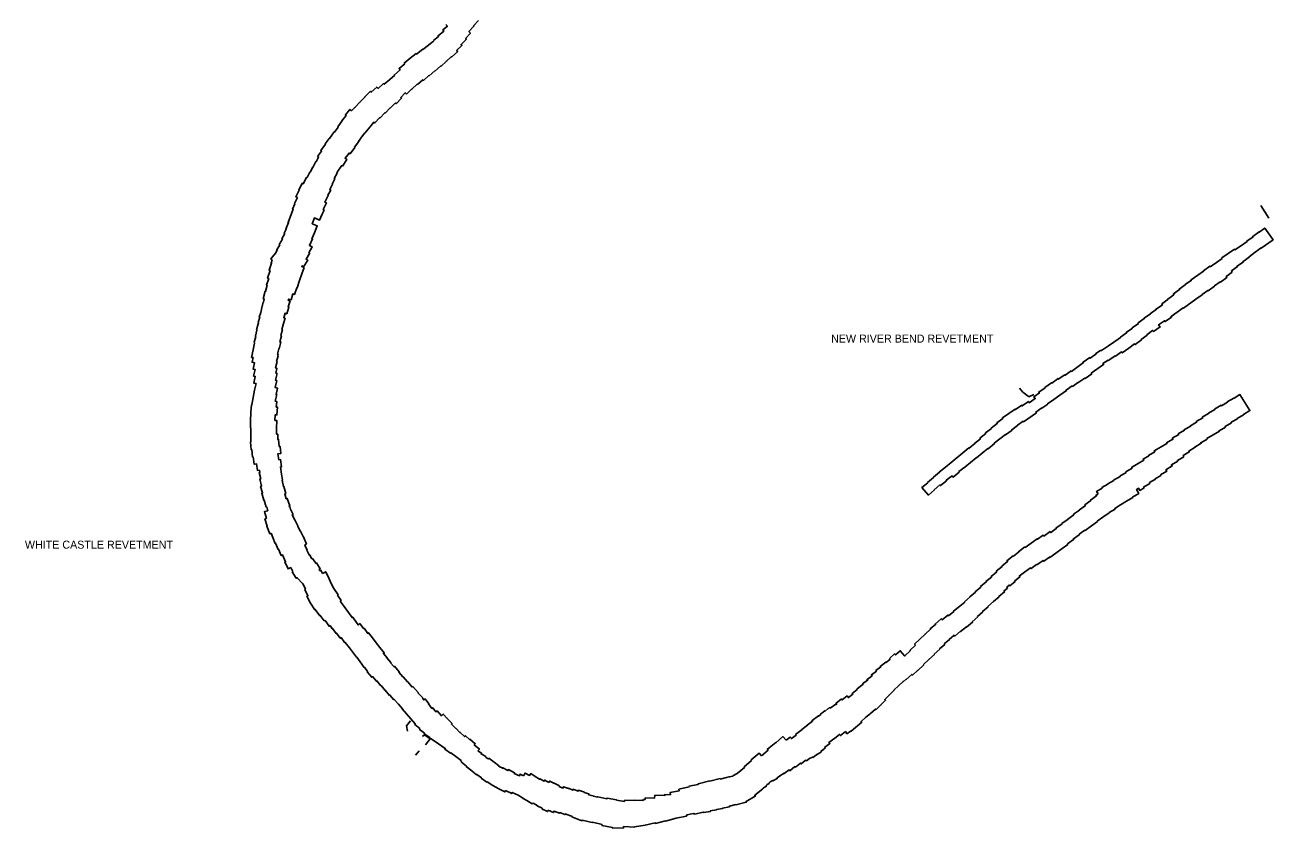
# Model space of a CAD drawing. Extents: x 2650582 to 3923188, y 277893 to 989177.
# Drawn here: x 3328264 to 3353216, y 609154 to 625211 of the extents above; entities that cross this region are included whole.
import ezdxf

# ---------------------------------------------------------------- set-up
doc = ezdxf.new("R2010")
doc.units = 0
doc.layers.add('Level 3', color=7, linetype='Continuous')

msp = doc.modelspace()

# ---------------------------------------------------------------- linework, layer by layer
at = {"layer": 'Level 3'}
for points in [[(3335892, 623830), (3335995, 623932), (3336000, 623927), (3336106, 624026), (3336111, 624021), (3336216, 624117), (3336229, 624103), (3336339, 624200), (3336344, 624195), (3336455, 624292), (3336457, 624289), (3336569, 624390), (3336577, 624381), (3336693, 624484), (3336689, 624489), (3336787, 624577), (3336792, 624570), (3336915, 624678), (3336894, 624701), (3337001, 624801), (3336982, 624821), (3337089, 624927), (3337073, 624943), (3337170, 625050), (3337138, 625079), (3337238, 625188), (3337233, 625192), (3337331, 625302)], [(3336677, 625219), (3336708, 625186), (3336619, 625114), (3336639, 625089), (3336523, 624996), (3336533, 624983), (3336432, 624900), (3336435, 624896), (3336329, 624809), (3336331, 624806), (3336221, 624720), (3336216, 624726), (3336093, 624629), (3336082, 624642), (3335964, 624546), (3335963, 624548), (3335846, 624449), (3335856, 624437), (3335743, 624343), (3335764, 624317), (3335650, 624214), (3335657, 624206)], [(3335657, 624206), (3335560, 624121), (3335558, 624123), (3335447, 624026), (3335435, 624040), (3335323, 623941), (3335296, 623970), (3335188, 623867), (3335169, 623886), (3335057, 623772), (3335060, 623769), (3334967, 623672), (3334965, 623674), (3334857, 623562), (3334859, 623560), (3334795, 623492)], [(3335013, 622997), (3335056, 623051), (3335060, 623048), (3335159, 623167), (3335156, 623170), (3335240, 623270), (3335259, 623253), (3335349, 623357), (3335357, 623350), (3335456, 623456), (3335464, 623449), (3335562, 623554), (3335568, 623548), (3335670, 623651), (3335685, 623636), (3335792, 623748), (3335777, 623763), (3335866, 623856), (3335892, 623830)], [(3334795, 623492), (3334759, 623521), (3334672, 623414), (3334684, 623404), (3334596, 623292), (3334602, 623287), (3334519, 623174), (3334525, 623170), (3334451, 623068), (3334446, 623072), (3334350, 622941), (3334348, 622943), (3334266, 622832), (3334270, 622829), (3334178, 622702), (3334195, 622689), (3334114, 622582)], [(3334531, 622309), (3334598, 622399), (3334609, 622391), (3334701, 622518), (3334663, 622545), (3334742, 622651), (3334763, 622636), (3334857, 622763), (3334853, 622766), (3334936, 622880), (3334930, 622884), (3335013, 622997), (3335013, 622997)], [(3334114, 622582), (3334133, 622568), (3334084, 622477), (3334082, 622478), (3334020, 622364), (3334017, 622366), (3333965, 622266), (3333961, 622269), (3333903, 622160), (3333895, 622164), (3333828, 622036), (3333806, 622046), (3333742, 621907), (3333744, 621906), (3333681, 621773), (3333710, 621758), (3333651, 621641)], [(3334203, 621427), (3334245, 621510), (3334228, 621519), (3334291, 621652), (3334262, 621665), (3334326, 621804), (3334322, 621806), (3334377, 621910), (3334358, 621920), (3334414, 622025), (3334406, 622029), (3334460, 622132), (3334446, 622139), (3334505, 622249), (3334500, 622253), (3334531, 622309)], [(3333651, 621641), (3333659, 621637), (3333615, 621531), (3333625, 621526), (3333572, 621386), (3333572, 621386), (3333525, 621264), (3333535, 621260), (3333482, 621131), (3333486, 621129), (3333445, 621046), (3333458, 621041), (3333401, 620934), (3333410, 620929), (3333346, 620821), (3333359, 620813), (3333297, 620713), (3333309, 620705), (3333274, 620650), (3333182, 620533), (3333209, 620512)], [(3352974, 621604), (3353134, 621349)], [(3333848, 620361), (3333796, 620381), (3333803, 620394), (3333834, 620374), (3333916, 620507), (3333884, 620526), (3333954, 620644), (3333942, 620652), (3334006, 620773), (3333950, 620803), (3334013, 620932), (3334002, 620938), (3334049, 621053), (3334051, 621053), (3334108, 621198), (3334007, 621237), (3334050, 621352), (3334155, 621309), (3334203, 621427)], [(3353069, 621451), (3353055, 621474)], [(3352400, 620270), (3352382, 620294), (3352505, 620379), (3352497, 620389), (3352622, 620476), (3352616, 620483), (3352740, 620570), (3352736, 620576), (3352860, 620665), (3352856, 620669), (3352976, 620754), (3352979, 620749), (3353216, 620915), (3353051, 621150), (3352941, 621070), (3352939, 621072), (3352811, 620982), (3352816, 620976), (3352694, 620889), (3352698, 620881), (3352562, 620788), (3352455, 620714), (3352443, 620729), (3352191, 620552), (3352198, 620543)], [(3333209, 620512), (3333185, 620449), (3333193, 620446), (3333143, 620306), (3333164, 620299), (3333115, 620147), (3333137, 620140), (3333093, 620011), (3333104, 620007), (3333070, 619884), (3333066, 619886), (3333023, 619733)], [(3333527, 619705), (3333534, 619731), (3333585, 619717), (3333617, 619834), (3333652, 619822), (3333698, 619956), (3333707, 619953), (3333755, 620102), (3333752, 620103), (3333800, 620237), (3333848, 620361)], [(3352198, 620543), (3352084, 620461), (3352082, 620463), (3351957, 620377), (3351952, 620385), (3351822, 620296), (3351828, 620287), (3351712, 620206), (3351710, 620208), (3351578, 620118), (3351584, 620108), (3351459, 620023), (3351462, 620018), (3351340, 619931), (3351347, 619919), (3351223, 619832), (3351233, 619816), (3351110, 619730), (3351115, 619722), (3350993, 619635), (3351005, 619618), (3350879, 619531), (3350884, 619526), (3350760, 619437), (3350764, 619432), (3350638, 619346), (3350641, 619341), (3350518, 619254), (3350525, 619243), (3350401, 619157), (3350405, 619151), (3350281, 619063), (3350288, 619053), (3350166, 618968), (3350168, 618965), (3350116, 618928), (3350034, 618872), (3349927, 618794), (3349924, 618797), (3349863, 618756), (3349783, 618700), (3349776, 618709)], [(3349918, 618508), (3349925, 618499), (3349936, 618506), (3350060, 618594), (3350063, 618590), (3350185, 618678), (3350200, 618655), (3350334, 618748), (3350331, 618752), (3350448, 618835), (3350456, 618822), (3350585, 618914), (3350579, 618921), (3350700, 619009), (3350695, 619018), (3350809, 619102), (3350823, 619083), (3350956, 619174), (3350929, 619216), (3351046, 619297), (3351057, 619279), (3351188, 619371), (3351177, 619385), (3351298, 619471), (3351301, 619466), (3351422, 619553), (3351425, 619550), (3351674, 619726), (3351673, 619728), (3351798, 619818), (3351797, 619820), (3351913, 619903), (3351917, 619897), (3352047, 619989), (3352045, 619993), (3352161, 620074), (3352164, 620070), (3352294, 620163), (3352281, 620180), (3352400, 620270)], [(3333023, 619733), (3333046, 619727), (3333032, 619670), (3333029, 619671), (3332992, 619526), (3332995, 619525), (3332978, 619461), (3332949, 619368), (3332957, 619366), (3332929, 619259), (3332931, 619258), (3332924, 619234), (3332927, 619233), (3332895, 619112), (3332902, 619110), (3332871, 618989), (3332876, 618988), (3332874, 618982), (3332878, 618981), (3332868, 618937), (3332849, 618866), (3332851, 618865), (3332848, 618852), (3332851, 618851), (3332824, 618713), (3332825, 618713), (3332796, 618565), (3332827, 618559)], [(3333323, 618593), (3333318, 618594), (3333324, 618625), (3333315, 618627), (3333337, 618736), (3333343, 618735), (3333379, 618869), (3333358, 618874), (3333390, 618996), (3333378, 618999), (3333410, 619119), (3333400, 619122), (3333431, 619243), (3333465, 619348), (3333436, 619358), (3333465, 619447), (3333497, 619437), (3333540, 619570), (3333526, 619574), (3333565, 619693), (3333527, 619705)], [(3332827, 618559), (3332805, 618467), (3332851, 618456), (3332826, 618331), (3332865, 618324), (3332835, 618191), (3332867, 618184), (3332838, 618050), (3332883, 618040), (3332853, 617907), (3332856, 617906), (3332826, 617763), (3332824, 617763), (3332802, 617615), (3332793, 617616), (3332780, 617467), (3332778, 617468), (3332770, 617292), (3332774, 617292), (3332771, 617157), (3332778, 617157), (3332780, 617023), (3332778, 617023), (3332780, 616876), (3332775, 616875), (3332789, 616719), (3332797, 616720), (3332816, 616572), (3332823, 616573), (3332848, 616426), (3332895, 616434), (3332916, 616302), (3332950, 616307)], [(3333395, 616230), (3333375, 616375), (3333394, 616378), (3333370, 616524), (3333340, 616519), (3333320, 616637), (3333380, 616645), (3333363, 616783), (3333346, 616781), (3333334, 616924), (3333319, 616923), (3333318, 617032), (3333294, 617032), (3333292, 617143), (3333293, 617143), (3333297, 617304), (3333262, 617304), (3333267, 617416), (3333301, 617413), (3333315, 617570), (3333286, 617572), (3333301, 617682), (3333269, 617686), (3333297, 617819), (3333283, 617822), (3333311, 617950), (3333267, 617960), (3333298, 618101), (3333275, 618106), (3333305, 618241), (3333282, 618249), (3333301, 618345), (3333274, 618356), (3333303, 618479), (3333294, 618481), (3333323, 618593)], [(3349776, 618709), (3349668, 618634), (3349673, 618627), (3349558, 618546), (3349550, 618559), (3349418, 618469), (3349425, 618459), (3349184, 618285), (3349180, 618294), (3349057, 618206), (3349051, 618215), (3348923, 618128), (3348917, 618139), (3348793, 618052), (3348789, 618058), (3348654, 617963), (3348658, 617958), (3348533, 617872), (3348546, 617854), (3348436, 617777), (3348461, 617741), (3348343, 617658), (3348326, 617683), (3348199, 617594), (3348191, 617608), (3348068, 617521), (3348060, 617532), (3347806, 617357), (3347815, 617343), (3347694, 617254), (3347703, 617241), (3347581, 617152), (3347586, 617145), (3347465, 617054), (3347472, 617044), (3347355, 616950)], [(3347517, 616738), (3347644, 616840), (3347639, 616846), (3347755, 616937), (3347753, 616939), (3347865, 617024), (3347870, 617016), (3347997, 617111), (3347991, 617119), (3348110, 617200), (3348106, 617206), (3348223, 617287), (3348230, 617278), (3348485, 617456), (3348475, 617472), (3348593, 617555), (3348596, 617551), (3348711, 617632), (3348707, 617636), (3348832, 617721), (3348830, 617724), (3348954, 617812), (3348956, 617809), (3349084, 617900), (3349078, 617909), (3349198, 617993), (3349205, 617983), (3349328, 618069), (3349330, 618066), (3349454, 618152), (3349460, 618144), (3349591, 618235), (3349582, 618248), (3349829, 618422), (3349816, 618439), (3349918, 618508)], [(3348149, 617950), (3348216, 617870), (3348319, 617789), (3348336, 617778), (3348434, 617820)], [(3351430, 616577), (3351416, 616600), (3351542, 616674), (3351532, 616692), (3351658, 616766), (3351654, 616772), (3351780, 616846), (3351772, 616859), (3351897, 616932), (3351893, 616940), (3352019, 617014), (3352016, 617018), (3352142, 617092), (3352138, 617098), (3352264, 617172), (3352256, 617185), (3352382, 617259), (3352378, 617266), (3352504, 617339), (3352500, 617345), (3352627, 617418), (3352625, 617422), (3352752, 617502), (3352553, 617820), (3352436, 617747), (3352433, 617752), (3352298, 617674), (3352302, 617666), (3352185, 617598), (3352181, 617606), (3352046, 617527), (3352049, 617522), (3351922, 617448), (3351926, 617441), (3351801, 617368), (3351809, 617354), (3351682, 617280), (3351688, 617269), (3351563, 617196), (3351566, 617189), (3351440, 617116), (3351445, 617108), (3351320, 617034), (3351329, 617020), (3351202, 616946)], [(3347355, 616950), (3347365, 616938), (3347249, 616844), (3347251, 616841), (3347139, 616749), (3347135, 616753), (3347017, 616655), (3347014, 616659), (3346779, 616464), (3346781, 616460), (3346668, 616368), (3346664, 616372), (3346543, 616272), (3346546, 616268), (3346426, 616169), (3346429, 616164), (3346309, 616061), (3346312, 616057), (3346197, 615961), (3346326, 615812), (3346446, 615916), (3346443, 615919), (3346555, 616015), (3346567, 616000), (3346690, 616099), (3346683, 616107), (3346798, 616196), (3346819, 616172), (3346943, 616272), (3346936, 616280), (3347052, 616369), (3347283, 616559), (3347287, 616554), (3347515, 616741), (3347517, 616738)], [(3351202, 616946), (3351213, 616927), (3351088, 616854), (3351095, 616842), (3350978, 616774), (3350977, 616775), (3350842, 616696), (3350853, 616677), (3350727, 616603), (3350731, 616596), (3350619, 616531), (3350632, 616509), (3350522, 616444), (3350521, 616445), (3350386, 616366), (3350397, 616347), (3350272, 616274), (3350278, 616264), (3350151, 616189), (3350156, 616182), (3350029, 616108), (3350031, 616104), (3349911, 616035), (3349913, 616032), (3349794, 615962), (3349800, 615951), (3349688, 615885), (3349717, 615836)], [(3349939, 615461), (3350059, 615531), (3350050, 615546), (3350169, 615616), (3350167, 615619), (3350286, 615688), (3350285, 615690), (3350411, 615764), (3350406, 615772), (3350532, 615846), (3350487, 615923), (3350526, 615947), (3350551, 615905), (3350637, 615956), (3350628, 615971), (3350754, 616045), (3350745, 616061), (3350864, 616131), (3350860, 616137), (3350973, 616203), (3350966, 616216), (3351092, 616289), (3351074, 616319), (3351200, 616393), (3351185, 616418), (3351312, 616492), (3351305, 616504), (3351430, 616577)], [(3332950, 616307), (3332960, 616267), (3332944, 616263), (3332976, 616133), (3332959, 616128), (3332995, 615993), (3332975, 615986), (3333015, 615854), (3332998, 615849), (3333040, 615710), (3333045, 615711), (3333087, 615572), (3333096, 615575), (3333120, 615499)], [(3333574, 615527), (3333557, 615581), (3333550, 615579), (3333544, 615590), (3333556, 615595), (3333503, 615744), (3333488, 615739), (3333460, 615837), (3333478, 615843), (3333436, 615982), (3333431, 615981), (3333405, 616108), (3333410, 616109), (3333392, 616230), (3333395, 616230)], [(3349717, 615836), (3349678, 615810), (3349687, 615797), (3349569, 615712), (3349575, 615704), (3349453, 615619), (3349464, 615603), (3349344, 615518), (3349349, 615512), (3349229, 615427), (3349235, 615418), (3349114, 615332), (3349117, 615328), (3348995, 615243), (3348999, 615237), (3348874, 615149), (3348881, 615140), (3348771, 615061), (3348757, 615081), (3348634, 614992), (3348619, 615012), (3348506, 614928), (3348499, 614937), (3348382, 614850), (3348380, 614852), (3348260, 614765), (3348254, 614774)], [(3333120, 615499), (3333052, 615481), (3333090, 615344), (3333062, 615336), (3333104, 615190), (3333098, 615187), (3333156, 615039), (3333184, 615050)], [(3333894, 614829), (3333833, 614975), (3333829, 614973), (3333772, 615092), (3333767, 615090), (3333717, 615191), (3333719, 615193), (3333668, 615301), (3333669, 615301), (3333608, 615418), (3333623, 615425), (3333574, 615527)], [(3348488, 614426), (3348494, 614417), (3348617, 614505), (3348630, 614487), (3348746, 614573), (3348753, 614563), (3348870, 614648), (3348871, 614647), (3349002, 614742), (3348999, 614746), (3349110, 614826), (3349104, 614835), (3349228, 614923), (3349221, 614933), (3349345, 615020), (3349340, 615027), (3349455, 615109), (3349458, 615105), (3349586, 615196), (3349584, 615199), (3349704, 615284), (3349701, 615288), (3349815, 615368), (3349814, 615369), (3349940, 615459), (3349939, 615461)], [(3333184, 615050), (3333216, 614963), (3333218, 614964), (3333263, 614844), (3333271, 614847), (3333324, 614724), (3333332, 614728), (3333388, 614602), (3333415, 614614), (3333473, 614479), (3333462, 614474), (3333524, 614336), (3333580, 614362)], [(3334211, 614246), (3334181, 614309), (3334159, 614298), (3334143, 614323), (3334166, 614338), (3334091, 614456), (3334076, 614447), (3334011, 614545), (3334000, 614538), (3333972, 614580), (3333956, 614614), (3333952, 614611), (3333939, 614630), (3333936, 614628), (3333899, 614710), (3333903, 614712), (3333857, 614813), (3333894, 614829)], [(3348254, 614774), (3348124, 614675), (3348128, 614668), (3348026, 614592), (3348023, 614596), (3347894, 614499), (3347908, 614480), (3347793, 614387), (3347798, 614381), (3347683, 614288), (3347692, 614278), (3347581, 614185), (3347590, 614173), (3347477, 614080), (3347481, 614075), (3347368, 613980), (3347375, 613972), (3347261, 613878), (3347268, 613870), (3347157, 613777), (3347160, 613774), (3347048, 613677), (3347053, 613671), (3346954, 613587), (3346951, 613590), (3346829, 613492), (3346833, 613486), (3346724, 613399), (3346714, 613411), (3346603, 613318), (3346584, 613340), (3346465, 613238), (3346472, 613230), (3346361, 613137), (3346369, 613127), (3346260, 613032), (3346262, 613030), (3346152, 612929), (3346154, 612927), (3346048, 612827), (3346067, 612808), (3345958, 612707), (3345964, 612700)], [(3333580, 614362), (3333616, 614280), (3333608, 614274), (3333689, 614147), (3333707, 614158), (3333815, 614043), (3333816, 614045)], [(3346234, 612415), (3346228, 612421), (3346337, 612521), (3346336, 612522), (3346445, 612625), (3346441, 612629), (3346553, 612731), (3346548, 612736), (3346651, 612825), (3346641, 612836), (3346745, 612923), (3346743, 612926), (3346839, 613008), (3346852, 612993), (3346964, 613088), (3346969, 613082), (3347084, 613174), (3347086, 613172), (3347208, 613270), (3347201, 613279), (3347312, 613374), (3347305, 613382), (3347417, 613479), (3347410, 613486), (3347520, 613578), (3347514, 613586), (3347629, 613681), (3347625, 613685), (3347739, 613780), (3347736, 613784), (3347847, 613876), (3347834, 613891), (3347910, 613953), (3347894, 613972), (3347942, 614013), (3347956, 613995), (3348055, 614075), (3348045, 614088), (3348154, 614176), (3348141, 614193), (3348246, 614272), (3348248, 614268), (3348366, 614356), (3348377, 614342), (3348488, 614426)], [(3334568, 613692), (3334587, 613705), (3334513, 613808), (3334524, 613815), (3334441, 613946), (3334440, 613946), (3334388, 614045), (3334386, 614044), (3334343, 614135), (3334344, 614136), (3334276, 614278), (3334211, 614246)], [(3333816, 614045), (3333871, 613932), (3333859, 613926), (3333920, 613799), (3333900, 613788), (3333972, 613650), (3333975, 613652), (3334059, 613520), (3334068, 613525), (3334158, 613399), (3334168, 613406), (3334248, 613295)], [(3334960, 613242), (3334922, 613214), (3334902, 613243), (3334907, 613246), (3334817, 613372), (3334802, 613361), (3334730, 613463), (3334730, 613463), (3334647, 613582), (3334647, 613582), (3334568, 613692)], [(3334248, 613295), (3334263, 613305), (3334343, 613190), (3334364, 613205)], [(3334364, 613205), (3334406, 613140), (3334413, 613144), (3334484, 613044), (3334493, 613050), (3334568, 612949), (3334584, 612961), (3334661, 612860), (3334667, 612866), (3334750, 612756), (3334752, 612758), (3334892, 612569), (3334896, 612571), (3334965, 612478), (3334963, 612476), (3335042, 612367), (3335049, 612372), (3335113, 612286), (3335106, 612280), (3335197, 612169), (3335214, 612183), (3335291, 612089), (3335299, 612095), (3335379, 612000), (3335382, 612002), (3335462, 611907), (3335463, 611909), (3335552, 611807), (3335559, 611813), (3335641, 611719), (3335648, 611725), (3335729, 611632), (3335731, 611633), (3335810, 611539), (3335806, 611534), (3335892, 611437), (3335892, 611437), (3335981, 611340), (3335975, 611334), (3336067, 611240), (3336057, 611225), (3336158, 611146), (3336145, 611129)], [(3335650, 612393), (3335635, 612381), (3335572, 612455), (3335580, 612462), (3335498, 612556), (3335503, 612560), (3335431, 612644), (3335446, 612656), (3335360, 612763), (3335360, 612763), (3335288, 612857), (3335286, 612856), (3335212, 612956), (3335210, 612954), (3335134, 613059), (3335117, 613046), (3335043, 613148), (3335034, 613141), (3334960, 613242)], [(3345964, 612700), (3345851, 612598), (3345856, 612593), (3345856, 612592), (3345762, 612697), (3345670, 612614), (3345651, 612636), (3345545, 612544)], [(3336210, 611751), (3336216, 611756), (3336121, 611860), (3336125, 611864), (3336017, 611982), (3336005, 611971), (3335916, 612077), (3335912, 612074), (3335824, 612178), (3335820, 612175), (3335739, 612272), (3335747, 612279), (3335650, 612393)], [(3345545, 612544), (3345558, 612529), (3345480, 612464), (3345473, 612472), (3345363, 612386), (3345372, 612375), (3345277, 612306), (3345287, 612293), (3345185, 612220), (3345200, 612200), (3345100, 612125), (3345111, 612110), (3345011, 612035), (3345021, 612022), (3345007, 612011), (3345001, 612017), (3344893, 611929), (3344899, 611922), (3344801, 611843), (3344812, 611830), (3344726, 611761), (3344699, 611795), (3344601, 611717), (3344587, 611735), (3344478, 611647), (3344492, 611629), (3344480, 611619)], [(3345878, 612132), (3345884, 612126), (3345994, 612226), (3346007, 612212), (3346110, 612307), (3346112, 612306), (3346234, 612415)], [(3344766, 611089), (3344782, 611090), (3344782, 611092), (3344784, 611089), (3344993, 611270), (3344978, 611287), (3345068, 611365), (3345070, 611362), (3345165, 611444), (3345168, 611441), (3345271, 611531), (3345278, 611524), (3345376, 611614), (3345374, 611617), (3345470, 611710), (3345454, 611726), (3345547, 611817), (3345545, 611819), (3345640, 611913), (3345639, 611914), (3345729, 612000), (3345731, 611998), (3345819, 612084), (3345822, 612080), (3345878, 612132)], [(3337318, 610697), (3337348, 610734), (3337247, 610816), (3337267, 610840), (3337158, 610928), (3337153, 610923), (3337069, 610999), (3337054, 610982), (3336966, 611067), (3336961, 611061), (3336876, 611148), (3336875, 611146), (3336791, 611233), (3336804, 611245), (3336707, 611346), (3336705, 611344), (3336625, 611432), (3336590, 611399), (3336503, 611496), (3336480, 611476), (3336415, 611559), (3336400, 611547), (3336332, 611634), (3336335, 611636), (3336262, 611736), (3336235, 611717), (3336210, 611751)], [(3344480, 611619), (3344472, 611630), (3344360, 611551), (3344351, 611562), (3344321, 611538), (3344319, 611541), (3344260, 611491), (3344254, 611498), (3344169, 611432), (3344174, 611426), (3344129, 611391), (3344125, 611397), (3343999, 611304), (3344009, 611291), (3343904, 611213), (3343908, 611208), (3343796, 611126), (3343799, 611122), (3343669, 611025)], [(3335973, 611298), (3335890, 611199), (3335914, 611094)], [(3336145, 611129), (3336254, 611048), (3336246, 611037), (3336355, 610961), (3336354, 610960), (3336464, 610883), (3336465, 610886), (3336667, 610746), (3336657, 610732), (3336774, 610651), (3336778, 610656), (3336879, 610586), (3336876, 610581), (3336957, 610527), (3336983, 610506), (3336975, 610496), (3336997, 610479)], [(3344015, 610563), (3344071, 610605), (3344099, 610621), (3344097, 610623), (3344179, 610673), (3344172, 610683), (3344215, 610715), (3344216, 610713), (3344230, 610728), (3344260, 610750), (3344250, 610763), (3344357, 610841), (3344338, 610866), (3344453, 610952), (3344453, 610953), (3344549, 611027), (3344567, 611003), (3344668, 611082), (3344698, 611040), (3344766, 611089)], [(3336214, 610983), (3336252, 611020), (3336362, 610936), (3336273, 610820)], [(3343483, 610908), (3343418, 610981), (3343278, 610856), (3343272, 610863), (3343106, 610733), (3343120, 610713), (3342987, 610596)], [(3343669, 611025), (3343681, 611009), (3343588, 610942), (3343564, 610972), (3343483, 610908)], [(3336147, 610696), (3336109, 610660), (3336072, 610614)], [(3337473, 610574), (3337478, 610583), (3337381, 610636), (3337391, 610652), (3337318, 610697)], [(3338233, 610195), (3338163, 610228), (3338148, 610195), (3338046, 610243), (3338054, 610260), (3337930, 610323), (3337918, 610302), (3337819, 610359), (3337812, 610347), (3337800, 610355), (3337801, 610357), (3337759, 610380), (3337729, 610399), (3337734, 610405), (3337641, 610470), (3337641, 610470), (3337535, 610550), (3337525, 610536), (3337504, 610548), (3337473, 610574)], [(3342987, 610596), (3342939, 610652), (3342781, 610515), (3342788, 610507), (3342642, 610377), (3342652, 610366), (3342503, 610245), (3342416, 610195), (3342417, 610193), (3342351, 610176), (3342351, 610177), (3342343, 610175), (3342342, 610178), (3342286, 610162), (3342163, 610134), (3342161, 610142), (3341956, 610092), (3341954, 610097), (3341721, 610037), (3341724, 610027), (3341538, 609988)], [(3343295, 610160), (3343355, 610194), (3343353, 610198), (3343441, 610248), (3343445, 610242), (3343543, 610316), (3343558, 610300), (3343656, 610384), (3343667, 610372), (3343768, 610453), (3343781, 610437), (3343861, 610501), (3343879, 610510), (3343887, 610499), (3343948, 610544), (3344008, 610572), (3344015, 610563)], [(3336997, 610479), (3336991, 610471), (3337092, 610389), (3337087, 610383), (3337196, 610295), (3337197, 610296), (3337292, 610220), (3337298, 610227), (3337390, 610158), (3337386, 610152), (3337500, 610072), (3337504, 610077), (3337620, 610005), (3337620, 610006), (3337738, 609938), (3337738, 609938), (3337859, 609877), (3337872, 609902), (3337995, 609844), (3338006, 609867), (3338124, 609812), (3338125, 609814), (3338210, 609759)], [(3338740, 610066), (3338656, 610113), (3338643, 610089), (3338559, 610139), (3338553, 610129), (3338464, 610184), (3338464, 610184), (3338375, 610242), (3338351, 610205), (3338263, 610252), (3338233, 610195)], [(3338953, 610000), (3338841, 610052), (3338839, 610049), (3338754, 610092), (3338740, 610066)], [(3341654, 609442), (3341655, 609433), (3341824, 609468), (3341827, 609469), (3341828, 609464), (3341967, 609485), (3341965, 609498), (3342087, 609517), (3342086, 609524), (3342211, 609544), (3342210, 609552), (3342350, 609581), (3342347, 609593), (3342477, 609623), (3342478, 609617), (3342684, 609671), (3342680, 609686), (3342863, 609791), (3342854, 609808), (3343016, 609940), (3343013, 609944), (3343027, 609957), (3343088, 609988), (3343079, 610004), (3343103, 610025), (3343144, 610047), (3343139, 610057), (3343163, 610079), (3343214, 610106), (3343218, 610098), (3343304, 610143), (3343295, 610160)], [(3340661, 609757), (3340660, 609724), (3340630, 609723), (3340630, 609713), (3340600, 609712), (3340600, 609706), (3340445, 609709), (3340445, 609705), (3340251, 609709), (3340249, 609686), (3340093, 609712), (3340093, 609715), (3339901, 609752), (3339898, 609740), (3339716, 609780), (3339714, 609772), (3339625, 609793), (3339626, 609796), (3339532, 609820), (3339538, 609840), (3339445, 609866), (3339447, 609870), (3339329, 609909), (3339324, 609894), (3339225, 609928), (3339220, 609914), (3339130, 609949), (3339127, 609941), (3339029, 609980), (3339017, 609950), (3338945, 609982), (3338953, 610000)], [(3341171, 609820), (3341055, 609823), (3341054, 609804), (3340857, 609811), (3340852, 609753), (3340661, 609757)], [(3341538, 609988), (3341541, 609975), (3341338, 609929), (3341345, 609901), (3341162, 609864), (3341171, 609820)], [(3338210, 609759), (3338211, 609762), (3338227, 609752), (3338222, 609743), (3338298, 609705), (3338297, 609703), (3338404, 609639), (3338410, 609649), (3338419, 609645), (3338421, 609648), (3338473, 609623), (3338506, 609605), (3338504, 609601), (3338606, 609549), (3338600, 609536)], [(3338600, 609536), (3338713, 609484), (3338725, 609510)], [(3338725, 609510), (3338829, 609464), (3338842, 609492), (3338948, 609449), (3338954, 609463), (3339060, 609422), (3339065, 609435), (3339173, 609398), (3339174, 609401), (3339202, 609391), (3339198, 609381), (3339399, 609301), (3339403, 609308), (3339606, 609263), (3339608, 609269), (3339803, 609227), (3339799, 609203), (3340008, 609165), (3340006, 609154), (3340231, 609156), (3340233, 609183), (3340451, 609173), (3340451, 609176), (3340661, 609208), (3340661, 609210), (3340865, 609255), (3340867, 609245), (3341068, 609296), (3341069, 609294), (3341284, 609351), (3341284, 609352), (3341490, 609393), (3341487, 609411), (3341507, 609415), (3341506, 609420), (3341622, 609443), (3341623, 609436), (3341654, 609442)]]:
    msp.add_lwpolyline(points, dxfattribs=at)

# ---------------------------------------------------------------- texts
for s, p in [('NEW RIVER BEND REVETMENT', (3344380, 618860)), ('WHITE CASTLE REVETMENT', (3328263, 614740))]:
    msp.add_text(s, height=160, dxfattribs=at).set_placement(p)

doc.saveas('drawing.dxf')
